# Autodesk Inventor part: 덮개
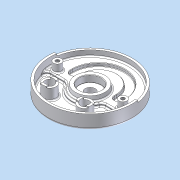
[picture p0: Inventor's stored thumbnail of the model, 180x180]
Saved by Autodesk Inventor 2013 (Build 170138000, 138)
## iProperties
Company: 한국ATC센터
Created: 2015-04
Part Number: 덮개
Document SubType Name: Modeling
Designer: KYOUNG IL JANG
Density: 2.71 g/cm^3
Material: 알루미늄-6061
Author: KYOUNG IL JANG
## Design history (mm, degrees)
sketch "스케치1"
  geometry: L1 (-59, -19)-(-59, 19); L2 (59, 19)-(59, -19); L3 (-41, 19)-(-41, -19); L4 (41, -19)-(41, 19); L5 (59, 5)-(41, 5); L6 (-41, 5)-(-59, 5); C1 r 90 at (0, 0); C2 r 95 at (0, 0); A1 r 59 centre (0, 19) between (59, 19) and (-59, 19); A2 r 59 centre (0, -19) between (-59, -19) and (59, -19); A3 r 41 centre (0, -19) between (-41, -19) and (41, -19); A4 r 41 centre (0, 19) between (41, 19) and (-41, 19); 2 further points
  constraints: 12 end point, 8 point on circle, 6 centre point, 4 point on line, 4 tangent, 2 parallel, 2 perpendicular, 1 coincident, 1 collinear, 1 horizontal alignment, 1 midpoint, 1 vertical, 1 vertical alignment, 3 other
  dimensions: "d2" = 180 diameter of C1; "d3" = 156 dimension on A2 A1; "d4" = 118 distance between parallel lines of L2 L1; "d5" = 18 distance between parallel lines of L2 L4; "d8" = 190 diameter of C2; "d121" = 5 distance from line of L5 point (0, 0)
extrude "돌출1" new body sketch "스케치1" distance "d6" = 14; taper "d7" = 0 deg
extrude "돌출2" join sketch "스케치1" distance "d9" = 13; taper "d10" = 0 deg
extrude "돌출3" cut sketch "스케치1" distance "d11" = 7; taper "d12" = 0 deg
sketch "스케치15"
  geometry: C1 r 26 at (0, 0); 1 further point
  constraints: 1 centre point, 1 coincident
  dimensions: "d123" = 52 diameter of C1
extrude "돌출13" join sketch "스케치15" distance "d124" = 12; taper "d125" = -7.5 deg
sketch "스케치2"
  geometry: C1 r 11.5 at (0, 0); 1 further point
  constraints: 1 centre point, 1 coincident
  dimensions: "d13" = 23 diameter of C1
extrude "돌출4" cut sketch "스케치2" stored distance "d14" = 7; taper "d15" = 0 deg
fillet "모깎기1"
fillet "모깎기2"
sketch "스케치3"
  geometry: L1 (-89.124, 12.526)-(-94.075, 13.221); L2 (89.124, 12.526)-(94.075, 13.221); L3 (0, 0)-(0, -90); A1 r 95 centre (0, 0) between (-94.075, 13.221) and (94.075, 13.221) reference; A2 r 90 centre (0, 0) between (-89.124, 12.526) and (89.124, 12.526) reference; 1 further point
  constraints: 6 end point, 5 point on circle, 1 point on line, 1 vertical, 1 other
  dimensions: "d16" = 196 deg dimension on L2 L1
extrude "돌출5" join sketch "스케치3" distance "d17" = 5; taper "d18" = 0 deg
hole "구멍1" diameter "d21" = 50; stored, may be unused: countersink angle "d25" = 90 deg, drill point angle "d27" = 0 deg; dims "d19" = 10, "d20" = 10, "d22" = 6, "d23" = 4, "d24" = 2, "d26" = 5
fillet "모깎기3" dims "d28" = 0.3
fillet "모깎기5" dims "d30" = 3
sketch "스케치4"
  geometry: C1 r 35 at (0, 0); C2 r 25 at (0, 0); 1 further point
  constraints: 2 centre point, 1 coincident
  dimensions: "d32" = 70 diameter of C1 (derived); "d36" = 10 radial gap between concentric circles of C1 C2
extrude "돌출6" join sketch "스케치4" distance "d33" = 10; taper "d34" = 0 deg
feature "면 기울기2" dims angle "d37" = 10 deg
chamfer "모따기1" distance "d39" = 1; stored, may be unused: second distance "d40" = 2, angle "d41" = 45 deg
fillet "모깎기7" dims "d42" = 5
sketch "스케치5"
  geometry: L1 (-38.833, -16)-(-88.566, -16); L2 (38.833, -16)-(88.566, -16); A1 r 90 centre (0, 0) between (-88.566, -16) and (88.566, -16) reference; A2 r 42 centre (0, 0) between (-38.833, -16) and (38.833, -16); 1 further point
  constraints: 4 end point, 4 point on circle, 1 centre point, 1 collinear, 1 horizontal, 1 point on line
  dimensions: "d43" = 48 radial gap between concentric circles of A1 A2; "d44" = 16 distance from line of point (0, 0) L1
extrude "돌출7" cut sketch "스케치5" stored distance "d45" = 10; taper "d46" = 0 deg
fillet "모깎기8" dims "d47" = 10
chamfer "모따기2" distance "d49" = 1; stored, may be unused: second distance "d50" = 2, angle "d51" = 45 deg
sketch "스케치8"
  geometry: C1 r 9 at (74, 0); C2 r 9 at (-74, 0); A1 r 74 centre (0, 0) between (74, 0) and (-74, 0); 1 further point
  constraints: 3 centre point, 2 horizontal alignment, 2 point on circle, 1 coincident, 1 equal radius
  dimensions: "d64" = 18 diameter of C1; "d65" = 148 diameter of A1
extrude "돌출9" join sketch "스케치8" stored distance "d66" = 5; taper "d67" = 0 deg
sketch "스케치11"
  geometry: C1 r 15 at (40, -52); C2 r 15 at (-40, -52); 1 further point
  constraints: 2 centre point, 1 equal radius, 1 horizontal alignment
  dimensions: "d82" = 52 vertical distance of point (0, 0) C1.centre; "d83" = 30 diameter of C1; "d84" = 80 distance of C2.centre C1.centre; "d85" = 40 horizontal distance of point (0, 0) C1.centre (= 0.5 x d84)
extrude "돌출10" join sketch "스케치11" stored distance "d86" = 10; taper "d87" = 0 deg
node "구멍3"
node "구멍5"
hole "구멍6" diameter "d92" = 20; stored, may be unused: countersink angle "d96" = 90 deg, drill point angle "d98" = 118 deg; dims "d90" = 10, "d91" = 10, "d93" = 6, "d94" = 4, "d95" = 2, "d97" = 8
hole "구멍7" diameter "d101" = 20; stored, may be unused: countersink angle "d105" = 90 deg, drill point angle "d107" = 118 deg; dims "d99" = 10, "d100" = 10, "d102" = 6, "d103" = 4, "d104" = 2, "d106" = 8
fillet "모깎기13" dims "d108" = 3
sketch "스케치13"
  geometry: L1 (-20.252, -58)-(-26, -58); L2 (-42, -58)-(-47.748, -58); L3 (-20.252, -46)-(-26, -46); L4 (-42, -46)-(-47.748, -46); L5 (-108, -65.748)-(-108, -60); L6 (-108, -44)-(-108, -38.252); L7 (-120, -44)-(-120, -38.252); L8 (-120, -60)-(-120, -65.748); A1 r 15 centre (-34, -52) between (-20.252, -58) and (-47.748, -58) reference; A2 r 10 centre (-34, -52) between (-26, -58) and (-42, -58) reference; A3 r 15 centre (-114, -52) between (-108, -65.748) and (-108, -38.252) reference; A4 r 10 centre (-114, -52) between (-108, -60) and (-108, -44) reference; 1 further point
  constraints: 16 end point, 16 point on circle, 3 equal length, 3 point on line, 2 collinear, 1 horizontal, 1 perpendicular
  dimensions: "d114" = 12 distance between parallel lines of L4 L2; "d115" = 6 distance from line of A1.centre L2 (= 0.5 x d114); "d116" = 12 distance between parallel lines of L8 L5 (= d114); "d117" = 6 distance from line of A3.centre L5 (= d115)
extrude "돌출12" join sketch "스케치13" distance "d118" = 3; taper "d119" = 0 deg
fillet "모깎기14" dims "d120" = 1
node "솔리드1"
sketch "스케치9"
  geometry: 1 further point
hole "구멍2" sketch "스케치9" diameter "d68" = 8.376; stored, may be unused: countersink angle "d72" = 90 deg, drill point angle "d74" = 120 deg; dims "d69" = 16, "d70" = 4, "d71" = 2, "d73" = 21
sketch "스케치10"
  geometry: 1 further point
hole "구멍4" sketch "스케치10" diameter "d75" = 8.376; stored, may be unused: countersink angle "d79" = 90 deg, drill point angle "d81" = 120 deg; dims "d76" = 16, "d77" = 4, "d78" = 2, "d80" = 21
